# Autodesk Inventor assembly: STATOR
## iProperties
Created: 2011-01
Part Number: STATOR
Document SubType Name: Assembly
Designer: eric
Mass: 66.4024 g
Surface Area: 199.252 cm^2
Volume: 66.4024 cm^3
Density: 1 g/cm^3
Norme de conversion: IGES 5.3
Nom du fichier: No Iges File Name specified
Préprocesseur: Autodesk Inventor 2011
Postprocesseur: Build: 342, Release: 2008 SP3 - Date: Tue 05/27/2008
Unités envoyées: MM
Incertitude: 0.01
Author: eric
